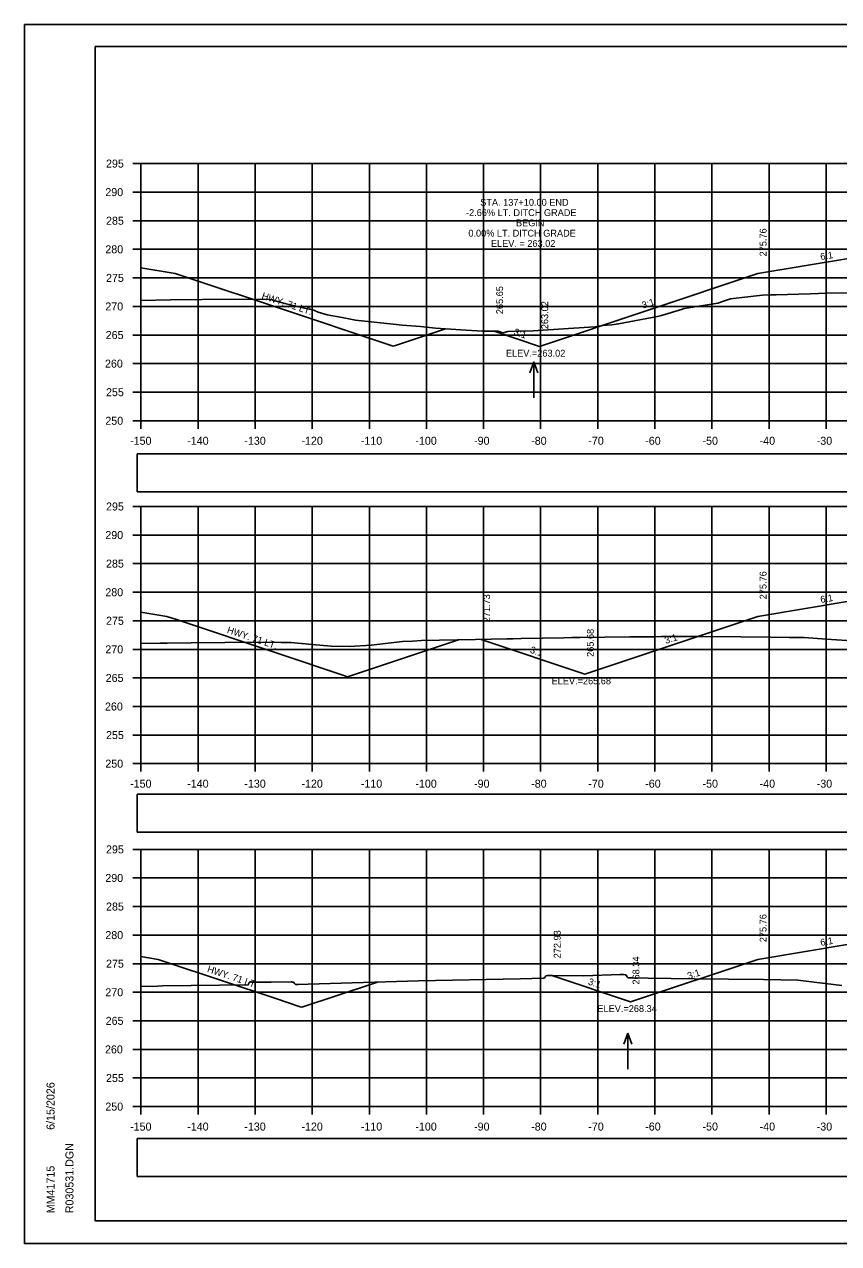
# Model space of a CAD drawing. Extents: x 285 to 4233, y -659 to 3710.
# Drawn here: x 2389.1 to 2531.7, y 2109.5 to 2322.9 of the extents above; entities that cross this region are included whole.
import ezdxf

# ---------------------------------------------------------------- set-up
doc = ezdxf.new("R2010")
doc.units = 0
for name, color, linetype in [('R_Axis', 7, 'Continuous'), ('R_Axis Annot', 7, 'Continuous'), ('R_Border', 7, 'Continuous'), ('R_Exist Surface', 7, 'Continuous'), ('R_Fin Surface', 7, 'Continuous'), ('R_Grid', 7, 'Continuous'), ('R_No Plot', 7, 'Continuous'), ('R_Water', 7, 'Continuous'), ('R_Water Annot', 7, 'Continuous'), ('R_Xsect Elev', 7, 'Continuous'), ('R_Xsect Slope', 7, 'Continuous')]:
    doc.layers.add(name, color=color, linetype=linetype)

msp = doc.modelspace()

# ---------------------------------------------------------------- linework, layer by layer
at = {"layer": 'R_Axis'}
for p, q in [((2408.1, 2298.53), (2409.5, 2298.53)), ((2409.5, 2253.53), (2409.5, 2298.53)), ((2408.1, 2293.53), (2409.5, 2293.53)), ((2408.1, 2288.53), (2409.5, 2288.53)), ((2408.1, 2283.53), (2409.5, 2283.53)), ((2408.1, 2278.53), (2409.5, 2278.53)), ((2408.1, 2273.53), (2409.5, 2273.53)), ((2408.1, 2268.53), (2409.5, 2268.53)), ((2408.1, 2263.53), (2409.5, 2263.53)), ((2408.1, 2258.53), (2409.5, 2258.53)), ((2408.1, 2253.53), (2409.5, 2253.53)), ((2409.5, 2253.53), (2709.5, 2253.53)), ((2409.5, 2252.13), (2409.5, 2253.53)), ((2419.5, 2252.13), (2419.5, 2253.53)), ((2429.5, 2252.13), (2429.5, 2253.53)), ((2439.5, 2252.13), (2439.5, 2253.53)), ((2449.5, 2252.13), (2449.5, 2253.53)), ((2459.5, 2252.13), (2459.5, 2253.53)), ((2469.5, 2252.13), (2469.5, 2253.53)), ((2479.5, 2252.13), (2479.5, 2253.53)), ((2489.5, 2252.13), (2489.5, 2253.53)), ((2499.5, 2252.13), (2499.5, 2253.53)), ((2509.5, 2252.13), (2509.5, 2253.53)), ((2519.5, 2252.13), (2519.5, 2253.53)), ((2529.5, 2252.13), (2529.5, 2253.53)), ((2408.1, 2238.53), (2409.5, 2238.53)), ((2409.5, 2193.53), (2409.5, 2238.53)), ((2408.1, 2233.53), (2409.5, 2233.53)), ((2408.1, 2228.53), (2409.5, 2228.53)), ((2408.1, 2223.53), (2409.5, 2223.53)), ((2408.1, 2218.53), (2409.5, 2218.53)), ((2408.1, 2213.53), (2409.5, 2213.53)), ((2408.1, 2208.53), (2409.5, 2208.53)), ((2408.1, 2203.53), (2409.5, 2203.53)), ((2408.1, 2198.53), (2409.5, 2198.53)), ((2408.1, 2193.53), (2409.5, 2193.53)), ((2409.5, 2193.53), (2709.5, 2193.53)), ((2409.5, 2192.13), (2409.5, 2193.53)), ((2419.5, 2192.13), (2419.5, 2193.53)), ((2429.5, 2192.13), (2429.5, 2193.53)), ((2439.5, 2192.13), (2439.5, 2193.53)), ((2449.5, 2192.13), (2449.5, 2193.53)), ((2459.5, 2192.13), (2459.5, 2193.53)), ((2469.5, 2192.13), (2469.5, 2193.53)), ((2479.5, 2192.13), (2479.5, 2193.53)), ((2489.5, 2192.13), (2489.5, 2193.53)), ((2499.5, 2192.13), (2499.5, 2193.53)), ((2509.5, 2192.13), (2509.5, 2193.53)), ((2519.5, 2192.13), (2519.5, 2193.53)), ((2529.5, 2192.13), (2529.5, 2193.53)), ((2408.1, 2178.53), (2409.5, 2178.53)), ((2409.5, 2133.53), (2409.5, 2178.53)), ((2408.1, 2173.53), (2409.5, 2173.53)), ((2408.1, 2168.53), (2409.5, 2168.53)), ((2408.1, 2163.53), (2409.5, 2163.53)), ((2408.1, 2158.53), (2409.5, 2158.53)), ((2408.1, 2153.53), (2409.5, 2153.53)), ((2408.1, 2148.53), (2409.5, 2148.53)), ((2408.1, 2143.53), (2409.5, 2143.53)), ((2408.1, 2138.53), (2409.5, 2138.53)), ((2408.1, 2133.53), (2409.5, 2133.53)), ((2409.5, 2133.53), (2709.5, 2133.53)), ((2409.5, 2132.13), (2409.5, 2133.53)), ((2419.5, 2132.13), (2419.5, 2133.53)), ((2429.5, 2132.13), (2429.5, 2133.53)), ((2439.5, 2132.13), (2439.5, 2133.53)), ((2449.5, 2132.13), (2449.5, 2133.53)), ((2459.5, 2132.13), (2459.5, 2133.53)), ((2469.5, 2132.13), (2469.5, 2133.53)), ((2479.5, 2132.13), (2479.5, 2133.53)), ((2489.5, 2132.13), (2489.5, 2133.53)), ((2499.5, 2132.13), (2499.5, 2133.53)), ((2509.5, 2132.13), (2509.5, 2133.53)), ((2519.5, 2132.13), (2519.5, 2133.53)), ((2529.5, 2132.13), (2529.5, 2133.53))]:
    msp.add_line(p, q, dxfattribs=at)
at = {"layer": 'R_Axis Annot'}
for points in [[(2408.87, 2241.08), (2536.56, 2241.08), (2536.56, 2247.73), (2408.87, 2247.73)], [(2408.87, 2181.52), (2536.56, 2181.52), (2536.56, 2188.18), (2408.87, 2188.18)], [(2408.87, 2121.28), (2536.56, 2121.28), (2536.56, 2127.94), (2408.87, 2127.94)]]:
    msp.add_lwpolyline(points, close=True, dxfattribs=at)
at = {"layer": 'R_Border'}
for p, q in [((2401.5, 2318.99), (2717.68, 2318.99)), ((2401.5, 2113.53), (2401.5, 2318.99)), ((2401.5, 2113.53), (2401.5, 2113.53)), ((2717.68, 2113.53), (2401.5, 2113.53))]:
    msp.add_line(p, q, dxfattribs=at)
at = {"layer": 'R_Exist Surface'}
for points in [[(2409.5, 2274.6), (2414.69, 2274.68), (2425.82, 2274.82), (2431.98, 2274.72), (2432.46, 2274.71), (2432.62, 2274.66), (2434.68, 2274.03), (2438.14, 2273.24), (2439.78, 2272.87), (2440.56, 2272.55), (2442.11, 2272.05), (2444.74, 2271.59), (2447.05, 2271.16), (2453.65, 2270.41), (2455.27, 2270.24), (2458.48, 2270), (2461.09, 2269.72), (2465.5, 2269.44), (2469.31, 2269.19), (2470.87, 2269.18), (2472.05, 2269.18), (2472.86, 2268.89), (2473.77, 2269.16), (2475.06, 2269.21), (2478.19, 2269.26), (2484.35, 2269.65), (2488.96, 2269.97), (2490.36, 2270.17), (2491.99, 2270.33), (2493.15, 2270.49), (2499.94, 2271.75), (2500.66, 2271.96), (2504.33, 2273.08), (2504.55, 2273.15), (2504.74, 2273.19), (2505.4, 2273.31), (2510.55, 2274.1), (2511.69, 2274.51), (2512.75, 2274.84), (2514.71, 2275.08), (2518.36, 2275.49), (2519.82, 2275.55), (2520.71, 2275.59), (2526.72, 2275.76), (2529.61, 2275.85), (2534.95, 2275.94)], [(2409.5, 2214.54), (2412.94, 2214.62), (2414.09, 2214.64), (2418.33, 2214.67), (2430.08, 2214.78), (2434.06, 2214.73), (2435.78, 2214.71), (2439.5, 2214.41), (2442.82, 2214.08), (2446.01, 2214.01), (2449.84, 2214.25), (2455.31, 2214.89), (2457.07, 2214.99), (2458.66, 2215.06), (2468.08, 2215.24), (2473.55, 2215.36), (2474.69, 2215.39), (2476.11, 2215.41), (2483.53, 2215.56), (2484.95, 2215.58), (2486.36, 2215.59), (2495.09, 2215.72), (2496.38, 2215.72), (2499.49, 2215.75), (2500.64, 2215.76), (2501.78, 2215.78), (2502.77, 2215.79), (2503.56, 2215.8), (2507.98, 2215.78), (2514.58, 2215.72), (2519.78, 2215.67), (2523.05, 2215.63), (2525.66, 2215.6), (2529.58, 2215.29), (2534.84, 2214.95)], [(2409.5, 2154.53), (2412.45, 2154.62), (2413.3, 2154.63), (2428.28, 2154.84), (2428.37, 2155.07), (2428.47, 2155.29), (2428.58, 2155.32), (2428.7, 2155.34), (2428.82, 2155.33), (2428.9, 2155.32), (2432.33, 2155.32), (2435.81, 2155.33), (2435.89, 2155.33), (2435.97, 2155.32), (2436.1, 2155.3), (2436.23, 2155.27), (2436.39, 2155.07), (2436.55, 2154.89), (2436.55, 2154.89), (2436.55, 2154.89), (2437.03, 2154.88), (2437.03, 2154.88), (2438.78, 2154.94), (2458.08, 2155.51), (2475.9, 2155.89), (2480.07, 2155.97), (2480.26, 2156.18), (2480.36, 2156.33), (2480.42, 2156.42), (2480.65, 2156.46), (2480.68, 2156.46), (2481.57, 2156.47), (2487.08, 2156.41), (2493.44, 2156.61), (2494.02, 2156.63), (2494.32, 2156.59), (2494.43, 2156.57), (2494.66, 2156.23), (2494.82, 2156.05), (2495.37, 2156.05), (2495.57, 2156.05), (2498.31, 2156.01), (2506.36, 2155.88), (2512.39, 2155.82), (2518.54, 2155.77), (2521.54, 2155.7), (2524.52, 2155.65), (2529.3, 2155.09), (2532.24, 2154.73)]]:
    msp.add_lwpolyline(points, dxfattribs=at)
at = {"layer": 'R_Fin Surface'}
for points in [[(2471.37, 2269.18), (2479.27, 2266.55), (2517.5, 2279.29), (2541.5, 2283.29), (2547.5, 2283.53), (2571.5, 2283.05), (2573.5, 2283.01), (2581.5, 2282.69), (2601.5, 2279.36), (2641.48, 2266.03), (2649.57, 2268.73)], [(2409.5, 2280.29), (2415.5, 2279.29), (2417.43, 2278.65), (2434.63, 2272.92), (2451.74, 2267.22), (2453.69, 2266.56), (2454.11, 2266.7), (2462.84, 2269.6)], [(2469.09, 2215.26), (2487.25, 2209.21), (2517.5, 2219.29), (2541.5, 2223.29), (2547.5, 2223.53), (2571.5, 2223.05), (2573.5, 2223.01), (2581.5, 2222.69), (2601.5, 2219.36), (2640.65, 2206.31), (2647.21, 2208.49)], [(2409.5, 2220.04), (2414.02, 2219.29), (2415.71, 2218.73), (2433.88, 2212.67), (2444.67, 2209.08), (2445.7, 2208.73), (2463.37, 2214.61), (2465.09, 2215.18)], [(2481.45, 2156.47), (2495.24, 2151.87), (2517.5, 2159.29), (2541.5, 2163.29), (2547.5, 2163.53), (2571.5, 2163.05), (2573.5, 2163.01), (2581.5, 2162.69), (2601.5, 2159.36), (2639.79, 2146.6), (2643.93, 2147.98)], [(2409.5, 2159.8), (2412.53, 2159.29), (2413.95, 2158.82), (2433.14, 2152.42), (2437.38, 2151.01), (2437.7, 2150.9), (2450.22, 2155.07), (2450.91, 2155.3)]]:
    msp.add_lwpolyline(points, dxfattribs=at)
at = {"layer": 'R_Grid'}
for p, q in [((2409.5, 2298.53), (2709.5, 2298.53)), ((2409.5, 2253.53), (2409.5, 2298.53)), ((2419.5, 2253.53), (2419.5, 2298.53)), ((2429.5, 2253.53), (2429.5, 2298.53)), ((2439.5, 2253.53), (2439.5, 2298.53)), ((2449.5, 2253.53), (2449.5, 2298.53)), ((2459.5, 2253.53), (2459.5, 2298.53)), ((2469.5, 2253.53), (2469.5, 2298.53)), ((2479.5, 2253.53), (2479.5, 2298.53)), ((2489.5, 2253.53), (2489.5, 2298.53)), ((2499.5, 2253.53), (2499.5, 2298.53)), ((2509.5, 2253.53), (2509.5, 2298.53)), ((2519.5, 2253.53), (2519.5, 2298.53)), ((2529.5, 2253.53), (2529.5, 2298.53)), ((2409.5, 2293.53), (2709.5, 2293.53)), ((2409.5, 2288.53), (2709.5, 2288.53)), ((2409.5, 2283.53), (2709.5, 2283.53)), ((2409.5, 2278.53), (2709.5, 2278.53)), ((2409.5, 2273.53), (2709.5, 2273.53)), ((2409.5, 2268.53), (2709.5, 2268.53)), ((2409.5, 2263.53), (2709.5, 2263.53)), ((2409.5, 2258.53), (2709.5, 2258.53)), ((2409.5, 2253.53), (2709.5, 2253.53)), ((2409.5, 2238.53), (2709.5, 2238.53)), ((2409.5, 2193.53), (2409.5, 2238.53)), ((2419.5, 2193.53), (2419.5, 2238.53)), ((2429.5, 2193.53), (2429.5, 2238.53)), ((2439.5, 2193.53), (2439.5, 2238.53)), ((2449.5, 2193.53), (2449.5, 2238.53)), ((2459.5, 2193.53), (2459.5, 2238.53)), ((2469.5, 2193.53), (2469.5, 2238.53)), ((2479.5, 2193.53), (2479.5, 2238.53)), ((2489.5, 2193.53), (2489.5, 2238.53)), ((2499.5, 2193.53), (2499.5, 2238.53)), ((2509.5, 2193.53), (2509.5, 2238.53)), ((2519.5, 2193.53), (2519.5, 2238.53)), ((2529.5, 2193.53), (2529.5, 2238.53)), ((2409.5, 2233.53), (2709.5, 2233.53)), ((2409.5, 2228.53), (2709.5, 2228.53)), ((2409.5, 2223.53), (2709.5, 2223.53)), ((2409.5, 2218.53), (2709.5, 2218.53)), ((2409.5, 2213.53), (2709.5, 2213.53)), ((2409.5, 2208.53), (2709.5, 2208.53)), ((2409.5, 2203.53), (2709.5, 2203.53)), ((2409.5, 2198.53), (2709.5, 2198.53)), ((2409.5, 2193.53), (2709.5, 2193.53)), ((2409.5, 2178.53), (2709.5, 2178.53)), ((2409.5, 2133.53), (2409.5, 2178.53)), ((2419.5, 2133.53), (2419.5, 2178.53)), ((2429.5, 2133.53), (2429.5, 2178.53)), ((2439.5, 2133.53), (2439.5, 2178.53)), ((2449.5, 2133.53), (2449.5, 2178.53)), ((2459.5, 2133.53), (2459.5, 2178.53)), ((2469.5, 2133.53), (2469.5, 2178.53)), ((2479.5, 2133.53), (2479.5, 2178.53)), ((2489.5, 2133.53), (2489.5, 2178.53)), ((2499.5, 2133.53), (2499.5, 2178.53)), ((2509.5, 2133.53), (2509.5, 2178.53)), ((2519.5, 2133.53), (2519.5, 2178.53)), ((2529.5, 2133.53), (2529.5, 2178.53)), ((2409.5, 2173.53), (2709.5, 2173.53)), ((2409.5, 2168.53), (2709.5, 2168.53)), ((2409.5, 2163.53), (2709.5, 2163.53)), ((2409.5, 2158.53), (2709.5, 2158.53)), ((2409.5, 2153.53), (2709.5, 2153.53)), ((2409.5, 2148.53), (2709.5, 2148.53)), ((2409.5, 2143.53), (2709.5, 2143.53)), ((2409.5, 2138.53), (2709.5, 2138.53)), ((2409.5, 2133.53), (2709.5, 2133.53))]:
    msp.add_line(p, q, dxfattribs=at)
at = {"layer": 'R_No Plot'}
for p, q in [((2389.1, 2322.89), (2722.43, 2322.89)), ((2389.1, 2109.55), (2722.43, 2109.55))]:
    msp.add_line(p, q, dxfattribs=at)
for points in [[(2389.09, 2322.89), (2722.43, 2322.89), (2722.43, 2109.55), (2389.09, 2109.55)], [(2635.42, 2318.99), (2655.04, 2318.99), (2655.04, 2309.11), (2671.15, 2309.11), (2694.35, 2309.11), (2694.47, 2280.96), (2717.68, 2280.96), (2717.68, 2113.53), (2401.5, 2113.53), (2401.5, 2318.99)]]:
    msp.add_lwpolyline(points, close=True, dxfattribs=at)
at = {"layer": 'R_Water Annot'}
for p, q in [((2478.31, 2263.82), (2477.61, 2261.9)), ((2478.31, 2257.54), (2478.31, 2263.82)), ((2478.31, 2263.82), (2479.01, 2261.9)), ((2494.75, 2146.39), (2494.05, 2144.47)), ((2494.75, 2140.1), (2494.75, 2146.39)), ((2494.75, 2146.39), (2495.45, 2144.47))]:
    msp.add_line(p, q, dxfattribs=at)

# ---------------------------------------------------------------- texts
at = {"layer": 'R_Axis Annot'}
for s, p in [('295', (2403.39, 2297.83)), ('290', (2403.27, 2292.83)), ('285', (2403.39, 2287.83)), ('280', (2403.27, 2282.83)), ('275', (2403.39, 2277.83)), ('270', (2403.27, 2272.83)), ('265', (2403.33, 2267.83)), ('260', (2403.21, 2262.83)), ('255', (2403.39, 2257.83)), ('250', (2403.27, 2252.83)), ('-150', (2407.61, 2249.33)), ('-140', (2417.61, 2249.33)), ('-130', (2427.61, 2249.33)), ('-120', (2437.61, 2249.33)), ('-110', (2448.01, 2249.33)), ('-100', (2457.56, 2249.33)), ('-90', (2467.84, 2249.33)), ('-80', (2477.84, 2249.33)), ('-70', (2487.84, 2249.33)), ('-60', (2497.81, 2249.33)), ('-50', (2507.84, 2249.33)), ('-40', (2517.84, 2249.33)), ('-30', (2527.84, 2249.33)), ('295', (2403.39, 2237.83)), ('290', (2403.27, 2232.83)), ('285', (2403.39, 2227.83)), ('280', (2403.27, 2222.83)), ('275', (2403.39, 2217.83)), ('270', (2403.27, 2212.83)), ('265', (2403.33, 2207.83)), ('260', (2403.21, 2202.83)), ('255', (2403.39, 2197.83)), ('250', (2403.27, 2192.83)), ('-150', (2407.61, 2189.33)), ('-140', (2417.61, 2189.33)), ('-130', (2427.61, 2189.33)), ('-120', (2437.61, 2189.33)), ('-110', (2448.01, 2189.33)), ('-100', (2457.56, 2189.33)), ('-90', (2467.84, 2189.33)), ('-80', (2477.84, 2189.33)), ('-70', (2487.84, 2189.33)), ('-60', (2497.81, 2189.33)), ('-50', (2507.84, 2189.33)), ('-40', (2517.84, 2189.33)), ('-30', (2527.84, 2189.33)), ('295', (2403.39, 2177.83)), ('290', (2403.27, 2172.83)), ('285', (2403.39, 2167.83)), ('280', (2403.27, 2162.83)), ('275', (2403.39, 2157.83)), ('270', (2403.27, 2152.83)), ('265', (2403.33, 2147.83)), ('260', (2403.21, 2142.83)), ('255', (2403.39, 2137.83)), ('250', (2403.27, 2132.83)), ('-150', (2407.61, 2129.33)), ('-140', (2417.61, 2129.33)), ('-130', (2427.61, 2129.33)), ('-120', (2437.61, 2129.33)), ('-110', (2448.01, 2129.33)), ('-100', (2457.56, 2129.33)), ('-90', (2467.84, 2129.33)), ('-80', (2477.84, 2129.33)), ('-70', (2487.84, 2129.33)), ('-60', (2497.81, 2129.33)), ('-50', (2507.84, 2129.33)), ('-40', (2517.84, 2129.33)), ('-30', (2527.84, 2129.33))]:
    msp.add_text(s, height=1.4, dxfattribs=at).set_placement(p)
at = {"layer": 'R_Border'}
for s, p in [('6/15/2026', (2394.37, 2129.46)), ('R030531.DGN', (2397.69, 2114.86)), ('MM41715', (2394.37, 2114.86))]:
    msp.add_text(s, height=1.4, rotation=90, dxfattribs=at).set_placement(p)
at = {"layer": 'R_Water'}
for p in [(2430.55, 2274.91), (2424.48, 2216.44), (2421.01, 2157.1)]:
    msp.add_text('HWY. 71 LT.', height=1.2, rotation=341.5669, dxfattribs=at).set_placement(p)
at = {"layer": 'R_Xsect Elev'}
for s, p in [('STA. 137+10.00 END', (2468.92, 2291.15)), ('-2.66% LT. DITCH GRADE', (2466.43, 2289.35)), ('BEGIN', (2475.18, 2287.55)), ('0.00% LT. DITCH GRADE', (2466.84, 2285.75)), ('ELEV. = 263.02', (2470.79, 2283.95)), ('ELEV.=263.02', (2473.42, 2264.75)), ('ELEV.=265.68', (2481.42, 2207.41)), ('ELEV.=268.34', (2489.44, 2150.07))]:
    msp.add_text(s, height=1.2, dxfattribs=at).set_placement(p)
for s, p in [('275.76', (2519.05, 2282.29)), ('265.65', (2472.92, 2272.18)), ('263.02', (2480.82, 2269.55)), ('275.76', (2519.05, 2222.29)), ('271.73', (2470.64, 2218.26)), ('265.68', (2488.8, 2212.21)), ('275.76', (2519.05, 2162.29)), ('272.93', (2483, 2159.47)), ('268.34', (2496.79, 2154.87))]:
    msp.add_text(s, height=1.2, rotation=90, dxfattribs=at).set_placement(p)
at = {"layer": 'R_Xsect Slope'}
for s, rotation, p in [('6:1', 9.4623, (2528.57, 2281.64)), ('3:1', 18.4349, (2497.44, 2273.13)), ('3:1', 341.5651, (2474.69, 2268.6)), ('6:1', 9.4623, (2528.57, 2221.64)), ('3:1', 18.4349, (2501.43, 2214.46)), ('3:1', 341.5651, (2477.54, 2212.97)), ('6:1', 9.4623, (2528.57, 2161.64)), ('3:1', 18.4349, (2505.42, 2155.79)), ('3:1', 341.5651, (2487.71, 2154.91))]:
    msp.add_text(s, height=1.2, rotation=rotation, dxfattribs=at).set_placement(p)

doc.saveas('drawing.dxf')
